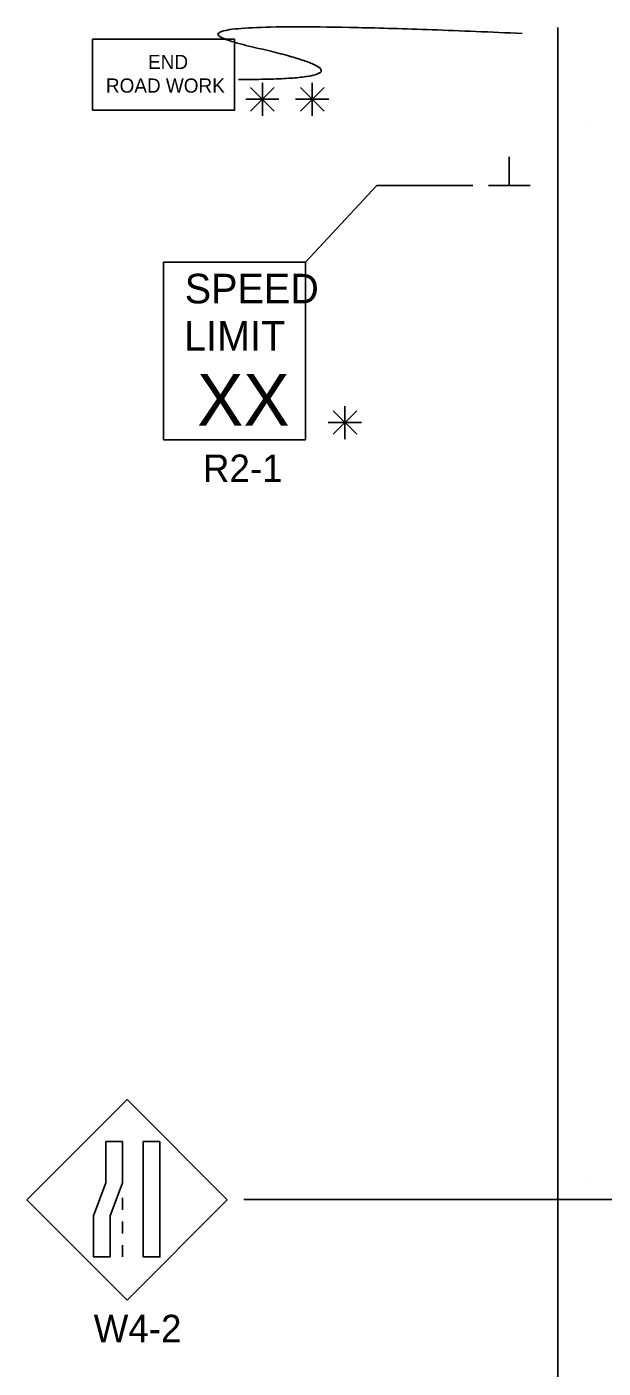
# Model space of a CAD drawing. Extents: x 16590 to 19508, y 5703 to 6974.
# Drawn here: x 17757.2 to 17913.2, y 6562.3 to 6925.5 of the extents above; entities that cross this region are included whole.
import ezdxf

# ---------------------------------------------------------------- set-up
doc = ezdxf.new("R2010")
doc.units = 0
for name, color, linetype in [('BORDER', 7, 'Continuous'), ('PAVT_EDGE_EX', 7, 'Continuous'), ('TRAFFIC_SIGNS_PR', 7, 'Continuous'), ('TYPICAL_TEXT_DIMEN_PR', 7, 'Continuous')]:
    doc.layers.add(name, color=color, linetype=linetype)

msp = doc.modelspace()

# ---------------------------------------------------------------- linework, layer by layer
at = {"layer": 'BORDER'}
for p, q in [((17909.54, 6899.78), (17909.54, 6899.78)), ((17909.54, 6612.74), (17909.54, 6612.74))]:
    msp.add_line(p, q, dxfattribs=at)
at = {"layer": 'PAVT_EDGE_EX'}
msp.add_line((17900.96, 6925.33), (17900.96, 6243.41), dxfattribs=at)
at = {"layer": 'TRAFFIC_SIGNS_PR'}
for p, q in [((17794.15, 6861.76), (17832.6, 6861.76)), ((17794.15, 6813.7), (17794.15, 6861.76)), ((17832.6, 6813.7), (17832.6, 6861.76)), ((17794.15, 6813.7), (17832.6, 6813.7)), ((17784.31, 6635.11), (17757.16, 6607.96)), ((17811.46, 6607.96), (17784.31, 6635.11)), ((17757.16, 6607.96), (17784.31, 6580.8)), ((17783.06, 6608.45), (17783.06, 6605.25)), ((17784.31, 6580.8), (17811.46, 6607.96)), ((17783.06, 6602.05), (17783.06, 6598.85)), ((17783.06, 6595.65), (17783.06, 6592.45))]:
    msp.add_line(p, q, dxfattribs=at)
for points in [[(17774.97, 6902.91), (17813.42, 6902.91), (17813.42, 6922.13), (17774.97, 6922.13)], [(17783.06, 6623.69), (17783.06, 6612.51), (17779.72, 6603.63), (17779.72, 6592.45), (17775.23, 6592.45), (17775.23, 6603.63), (17778.57, 6612.51), (17778.57, 6623.69)], [(17793.2, 6623.69), (17793.2, 6592.45), (17788.71, 6592.45), (17788.71, 6623.69)]]:
    msp.add_lwpolyline(points, close=True, dxfattribs=at)
msp.add_open_spline([(17814.53, 6911.21), (17857.04, 6911.21), (17780.52, 6928.63), (17891.31, 6923.69)], degree=2, dxfattribs=at)
at = {"layer": 'TYPICAL_TEXT_DIMEN_PR'}
for p, q in [((17817.78, 6909.04), (17824.15, 6902.66)), ((17824.15, 6909.04), (17817.78, 6902.66)), ((17820.96, 6905.85), (17820.96, 6910.31)), ((17831.28, 6909.04), (17837.66, 6902.66)), ((17837.66, 6909.04), (17831.28, 6902.66)), ((17834.47, 6905.85), (17834.47, 6910.31)), ((17820.96, 6905.85), (17816.43, 6905.85)), ((17820.96, 6905.85), (17824.15, 6905.85)), ((17820.96, 6905.85), (17825.44, 6905.85)), ((17820.96, 6905.85), (17820.96, 6901.35)), ((17834.47, 6905.85), (17829.94, 6905.85)), ((17834.47, 6905.85), (17837.66, 6905.85)), ((17834.47, 6905.85), (17838.95, 6905.85)), ((17834.47, 6905.85), (17834.47, 6901.35)), ((17887.83, 6882.5), (17887.83, 6890.28)), ((17832.6, 6861.76), (17851.96, 6882.5)), ((17851.96, 6882.5), (17877.96, 6882.5)), ((17882.21, 6882.5), (17893.46, 6882.5)), ((17840.12, 6821.53), (17846.5, 6815.16)), ((17846.5, 6821.53), (17840.12, 6815.16)), ((17843.31, 6818.34), (17843.31, 6822.8)), ((17843.31, 6818.34), (17838.78, 6818.34)), ((17843.31, 6818.34), (17846.5, 6818.34)), ((17843.31, 6818.34), (17847.79, 6818.34)), ((17843.31, 6818.34), (17843.31, 6813.84)), ((17815.96, 6607.97), (17921.15, 6607.97))]:
    msp.add_line(p, q, dxfattribs=at)

# ---------------------------------------------------------------- texts
at = {"layer": 'TRAFFIC_SIGNS_PR'}
for s, height, p in [('END', 3.836, (17789.99, 6914.05)), ('ROAD WORK', 3.836, (17778.58, 6907.66)), ('SPEED', 8.01, (17799.93, 6850.61)), ('LIMIT', 8.01, (17799.76, 6837.79)), ('XX', 14.048, (17803.28, 6817.46)), ('R2-1', 7.449, (17804.84, 6802.24)), ('W4-2', 7.44, (17775.27, 6569.36))]:
    msp.add_text(s, height=height, dxfattribs=at).set_placement(p)

doc.saveas('drawing.dxf')
